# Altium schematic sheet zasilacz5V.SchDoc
size A4
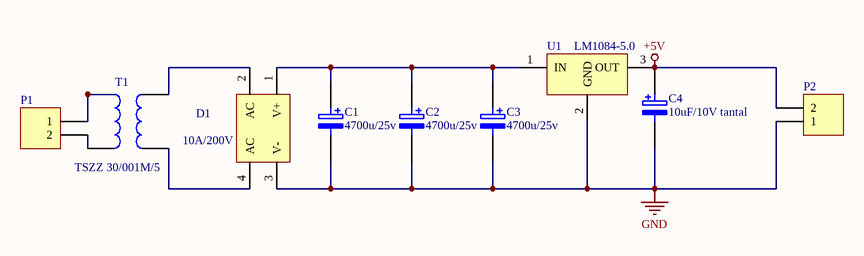
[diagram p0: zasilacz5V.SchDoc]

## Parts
C1  4700u/25v  [1000u/35v]
C2  4700u/25v  [1000u/35v]
C3  4700u/25v  [1000u/35v]
C4  10uF/10V tantal  [3528]
D1  10A/200V  [D-46_6A]
P1  (no value)  [wago]
P2  (no value)  [wago]
T1  TSZZ 30/001M/5  [TRANS]
U1  LM1084-5.0  [78XXST]

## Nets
+5V: C4.1 P2.2 U1.3(OUT)
GND: C1.2 C2.2 C3.2 C4.2 D1.3(V-) P2.1 U1.2(GND)
NetC1_1: C1.1 C2.1 C3.1 D1.1(V+) U1.1(IN)
NetD1_2: D1.2(AC) T1.3
NetD1_4: D1.4(AC) T1.4
NetP1_1: P1.1 T1.1
NetP1_2: P1.2 T1.2

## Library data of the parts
C1-C4 = ELECTRO2: Electrolytic Capacitor
D1 = Bridge2: Diode Bridge
P1 P2 = Header 2: Header, 2-Pin
T1 = Trans: Transformer
U1 = 78XX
